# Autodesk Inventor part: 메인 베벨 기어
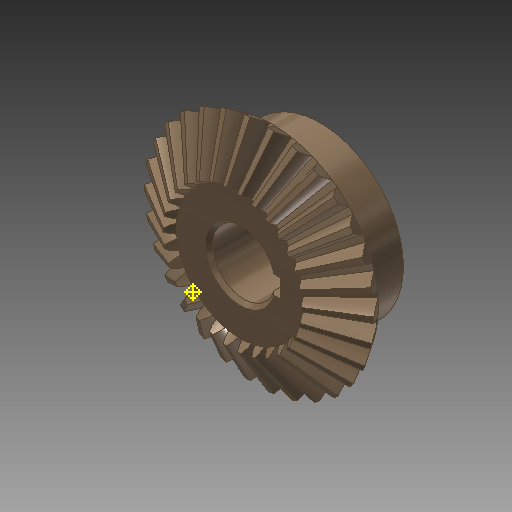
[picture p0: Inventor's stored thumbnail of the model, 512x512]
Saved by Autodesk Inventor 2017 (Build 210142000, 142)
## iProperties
Created: 2016-04
Part Number: 메인 베벨 기어
Material: 강철, 탄소
Document SubType Name: Modeling
Designer: mdu
Categories: <?xml version="1.0" encoding="UTF-16"?> <MemberInstance><Categories><FamilyTemplate><FamilyTemplateParameter ValueType="xs:double" Id="1" ObjectReferenceKey="da
Mass: 269.926 g
Surface Area: 108.837 cm^2
Volume: 34.2981 cm^3
Density: 7.87 g/cm^3
Appearance: 얼룩무늬
CustomPartVersion: 1
Author: mdu
Revision Number: 1
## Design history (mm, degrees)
node "맨 위 점"
node "메쉬 평면2"
sketch "톱니 본체 스케치"
  geometry: L1 (0, 0)-(28.669, -21.997); L2 (28.669, -21.997)-(31.109, -18.336); L3 (31.109, -18.336)-(0, 0); L4 (30, -20)-(0, 0); L5 (17.219, -13.212)-(18.685, -11.013); L6 (28.669, -21.997)-(17.219, -13.212); L7 (31.109, -18.336)-(18.685, -11.013); L8 (0, -39.387)-(0, 6.564) reference; L9 (0, -20)-(31.109, -20)
  constraints: 16 end point, 4 point on line, 3 perpendicular, 2 collinear, 1 horizontal alignment, 1 vertical alignment
  dimensions: "d0" = 60 diameter of L4.start L8 (= da_de); "d1" = 57.33744 diameter of L1.end L8 (= da_dfe); "d2" = 62.2188 diameter of L2.end L8 (= da_dae); "d3" = 14.4 distance between parallel lines of L2 L5 (= da_b); "d4" = 18.3359 vertical distance of L2.end L1.start (= da_ve)
revolve "톱니 본체" sketch "톱니 본체 스케치" stored, may be unused: angle "d5" = 90 deg
node "시작점"
node "톱니 평면"
sketch "시작 스케치"
  geometry: L1 (0, -23.505)-(0, 10.645) reference; L2 (-0.709, -2.928)-(0.709, -2.928); A1 r 19.188 centre (-19.457, -7.014) between (-0.709, -2.928) and (-3.232, 3.229); A2 r 19.188 centre (19.457, -7.014) between (3.232, 3.229) and (0.709, -2.928); A3 r 57.403 centre (0, -54.083) between (3.232, 3.229) and (-3.232, 3.229); 1 further point
  constraints: 6 point on circle, 3 centre point, 3 symmetric about line, 2 end point, 1 coincident, 1 perpendicular, 1 other
  dimensions: "d7" = 19.18795 radius of A1 (= fd_rr); "d8" = 19.45712 horizontal distance of point (0, -54.083) A1.centre (= fd_x); "d9" = 47.06905 vertical distance of point (0, -54.083) A1.centre (= fd_y); "d57" = 57.40327 radius of A3 (= 0.5 x fd_dva + 0.3 x da_he); "d58" = 51.15527 distance from line of A3.centre L2 (= 0.5 x fd_dva - 1.12 x da_he)
node "끝점"
  node "끝 평면"
sketch "3D 스케치 오른쪽"
  node "Helical Curve Right" dims "d65" = 229.90621 (computed from da_dm, da_delta, da_beta), "d66" = 31.5, "d67" = 60 (= da_de), "d68" = -9.82794 (= -da_delta), "d69" = 8.10972 (computed from fd_loft, da_delta)
node "끝 평면 오른쪽"
sketch "끝 스케치 오른쪽"
  geometry: L1 (0, -41.54)-(0, 13.178) reference; L2 (-0.422, -1.69)-(0.422, -1.69); A1 r 11.427 centre (-11.587, -4.123) between (-0.422, -1.69) and (-1.925, 1.977); A2 r 11.427 centre (11.587, -4.123) between (1.925, 1.977) and (0.422, -1.69); A3 r 34.184 centre (0, -32.153) between (1.925, 1.977) and (-1.925, 1.977); 1 further point
  constraints: 6 point on circle, 3 centre point, 3 symmetric about line, 2 end point, 1 coincident, 1 perpendicular, 1 other
  dimensions: "d70" = 11.58699 horizontal distance of A3.centre A1.centre (computed from fd_x, fd_ratio); "d71" = 28.03028 vertical distance of point (0, -32.153) A1.centre (computed from fd_y, fd_ratio); "d72" = 11.4267 radius of A1 (computed from fd_rr, fd_ratio); "d73" = 30.46369 distance from line of point (0, -32.153) L2 (computed from d58, fd_ratio); "d74" = 34.18446 radius of A3 (computed from d57, fd_ratio)
feature "로프트 오른쪽" sketch "끝 스케치 오른쪽" dims "d75" = 0, "d77" = 0, "d79" = 0, "d80" = 90 deg, "d85" = 20, "d92" = 90 deg, "d93" = 90 deg, "da_teethtype" = 0 [user parameter]
sketch "3D 스케치 왼쪽"
  node "Helical Curve Left" dims "d26" = 229.90621 (computed from da_dm, da_delta, da_beta), "d27" = 8.10972 (computed from fd_loft, da_delta), "d28" = 60 (= da_de), "d29" = -9.82794 (= -da_delta)
node "끝 평면 왼쪽"
sketch "끝 스케치 왼쪽" dims "d56" = 10.3728 (derived)
  geometry: L1 (0, -43.753)-(0, 15.405) reference; L2 (-0.422, -1.678)-(0.422, -1.678); A1 r 11.427 centre (-11.587, -4.111) between (-0.422, -1.678) and (-1.925, 1.988); A2 r 11.427 centre (11.587, -4.111) between (1.925, 1.988) and (0.422, -1.678); A3 r 34.184 centre (0, -32.142) between (1.925, 1.988) and (-1.925, 1.988); 2 further points; 1 other entity
  constraints: 6 point on circle, 3 centre point, 3 symmetric about line, 2 end point, 1 coincident, 2 other
  dimensions: "d30" = 11.4267 radius of A1 (computed from fd_rr, fd_ratio); "d31" = 11.58699 horizontal distance of point (0, -32.142) A1.centre (computed from fd_x, fd_ratio); "d32" = 28.03028 vertical distance of A1.centre point (0, -32.142) (computed from fd_y, fd_ratio); "d61" = 34.18446 radius of A3 (computed from d57, fd_ratio); "d62" = 30.46369 distance from line of point (0, -32.142) L2 (computed from d58, fd_ratio)
feature "로프트 왼쪽" sketch "끝 스케치 왼쪽" dims "d35" = 0, "d37" = 0, "d39" = 0, "d40" = 90 deg, "d84" = 10, "d90" = 90 deg, "d91" = 90 deg, "da_teethtype" = 0 [user parameter]
sketch "본체 스케치"
  geometry: L1 (0, -35.038)-(0, -19.531) reference; L2 (28.669, -21.997)-(17.219, -13.212) reference; L3 (17.219, -13.212)-(0, -13.212); L4 (28.669, -21.997)-(0, -21.997)
  constraints: 4 end point, 2 perpendicular, 2 point on line
revolve "본체 고정" sketch "본체 스케치" stored, may be unused: angle "d46" = 90 deg
feature "피치 지름" dims angle "d47" = 90 deg
sketch "스케치8"
  geometry: C1 r 22.5 at (0, 0); 1 further point
  constraints: 1 centre point, 1 coincident
  dimensions: "d94" = 45 diameter of C1
extrude "돌출1" join sketch "스케치8" distance "d95" = 13; taper "d96" = 0 deg
sketch "스케치9"
  geometry: 1 further point
hole "구멍1" sketch "스케치9" at (0, 0) diameter "d97" = 17; stored, may be unused: countersink angle "d101" = 90 deg, drill point angle "d103" = 118 deg; dims "d98" = 6, "d99" = 4, "d100" = 2, "d102" = 8
sketch "스케치10"
  geometry: L1 (8.124, 2.5)-(10.8, 2.5); L2 (10.8, 2.5)-(10.8, -2.5); L3 (10.8, -2.5)-(8.124, -2.5); A1 r 8.5 centre (0, 0) between (8.124, 2.5) and (8.124, -2.5) reference; 1 further point
  constraints: 6 end point, 2 parallel, 2 point on circle, 1 horizontal, 1 perpendicular
  dimensions: "d104" = 5 distance of L1.end L2.end; "d112" = 19.3 dimension on A1 L2
extrude "돌출2" cut sketch "스케치10" stored distance "d106" = 10; taper "d107" = 0 deg
chamfer "모따기1" distance "d108" = 1; stored, may be unused: second distance "d109" = 2, angle "d110" = 45 deg
fillet "모깎기1" dims "d111" = 2
body "Solid1"
feature "로프트" dims "d17" = 0, "d18" = 90 deg, "d19" = 0, "d20" = 90 deg, "d89" = 0, "da_teethtype" = 0 [user parameter]
pattern_circular "원형 패턴" dims angle "d22" = 360 deg, "d88" = 0, "da_teethtype" = 0 [user parameter]
pattern_circular "원형 패턴 오른쪽" dims angle "d82" = 360 deg, "da_teethtype" = 0 [user parameter]
pattern_circular "원형 패턴 왼쪽" dims angle "d42" = 360 deg, "da_teethtype" = 0 [user parameter]
sketch "끝 스케치"
  geometry: L1 (0, -15.359)-(0, 6.983) reference; L2 (-0.422, -1.69)-(0.422, -1.69); A1 r 11.427 centre (-11.587, -4.123) between (-0.422, -1.69) and (-1.925, 1.977); A2 r 11.427 centre (11.587, -4.123) between (1.925, 1.977) and (0.422, -1.69); A3 r 34.184 centre (0, -32.153) between (1.925, 1.977) and (-1.925, 1.977); 1 further point
  constraints: 6 point on circle, 3 centre point, 3 symmetric about line, 2 end point, 1 coincident, 1 other
  dimensions: "d12" = 11.4267 radius of A1 (computed from fd_rr, fd_ratio); "d15" = 11.58699 horizontal distance of A1.centre point (0, -32.153) (computed from fd_x, fd_ratio); "d16" = 28.03028 vertical distance of A1.centre point (0, -32.153) (computed from fd_y, fd_ratio); "d59" = 34.18446 radius of A3 (computed from d57, fd_ratio); "d60" = 30.46369 distance from line of A3.centre L2 (computed from d58, fd_ratio)
sketch "Sketch6"
  geometry: L1 (30, -20)-(0, 0) reference; L2 (0, -37.8)-(0, 6.3) reference
body "Srf1"
other parameters: "da_b" = 14.4 [user parameter; used in 2 equation terms], "da_de" = 60 [user parameter; used in 4 equation terms], "da_dae" = 62.2188 [user parameter; used in 2 equation terms], "da_dfe" = 57.33744 [user parameter; used in 1 equation term], "da_le" = 36.05551 [user parameter; used in 1 equation term], "da_omega" = 90 deg [user parameter; used in 1 equation term], "da_beta" = 0 [user parameter; used in 2 equation terms], "da_delta" = 9.82794 [user parameter; used in 8 equation terms], "da_alpha" = 20 deg [user parameter; used in 2 equation terms], "da_he" = 4.4 [user parameter; used in 4 equation terms], "da_ve" = 18.3359 [user parameter; used in 1 equation term], "fd_dv" = 108.16654 (computed from da_de, da_delta) [user parameter; used in 1 equation term], "fd_dva" = 112.16654 (computed from da_dae, da_delta) [user parameter; used in 3 equation terms], "fd_dvb" = 101.6433 (computed from fd_dv, da_alpha) [user parameter; used in 2 equation terms], "da_zv" = 540.83269 [user parameter; used in 1 equation term], "fd_loft" = 14.62 (= da_b + 0.05 x da_he) [user parameter; used in 4 equation terms], "fd_ratio" = 5.95514 (computed from da_le, fd_loft) [user parameter; used in 15 equation terms], "fd_rr" = 19.18795 (computed from fd_dd, fd_dvb) [user parameter; used in 6 equation terms], "fd_angle" = 0.29367 (computed from da_zv) [user parameter; used in 4 equation terms], "fd_x1" = 1.58802 (computed from da_dvw, fd_angle) [user parameter; used in 1 equation term], "fd_y1" = 54.05995 (computed from da_dvw, fd_angle) [user parameter; used in 1 equation term], "fd_x2" = 17.8691 (computed from fd_rr, fd_angle2, fd_angle) [user parameter; used in 1 equation term], "fd_y2" = 6.9909 (computed from fd_rr, fd_angle2, fd_angle) [user parameter; used in 1 equation term], "fd_x" = 19.45712 (= fd_x1 + fd_x2) [user parameter; used in 4 equation terms], "fd_y" = 47.06905 (= fd_y1 - fd_y2) [user parameter; used in 4 equation terms], "fd_angle2" = 3.43555 (computed from fd_dvb, fd_dd, da_alpha) [user parameter; used in 2 equation terms], "fd_dd" = 108.64654 (= fd_dva - 0.8 x da_he) [user parameter; used in 2 equation terms], "da_dvw" = 108.16654 [user parameter; used in 2 equation terms], "d11" = 14.62 (= fd_loft), "da_dm" = 48.01848 [user parameter; used in 2 equation terms], "da_x" = 0 [user parameter], "da_m" = 2 [user parameter], "d48" = 0, "d49" = 0, "d50" = 90 deg (= da_omega), "d51" = 6 deg (computed from da_z), "d52" = 0, "d53" = 0, "d54" = 0
